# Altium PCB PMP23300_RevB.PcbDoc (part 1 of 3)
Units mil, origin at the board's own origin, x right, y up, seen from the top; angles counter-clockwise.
Board outline 3834 x 2383 mil, 4 copper layers (Top Layer 1, Signal Layer 2, Signal Layer 3, Bottom Layer 1), stack 70.112 mil thick; 203 components, 126 nets, 635 pads, 226 vias.
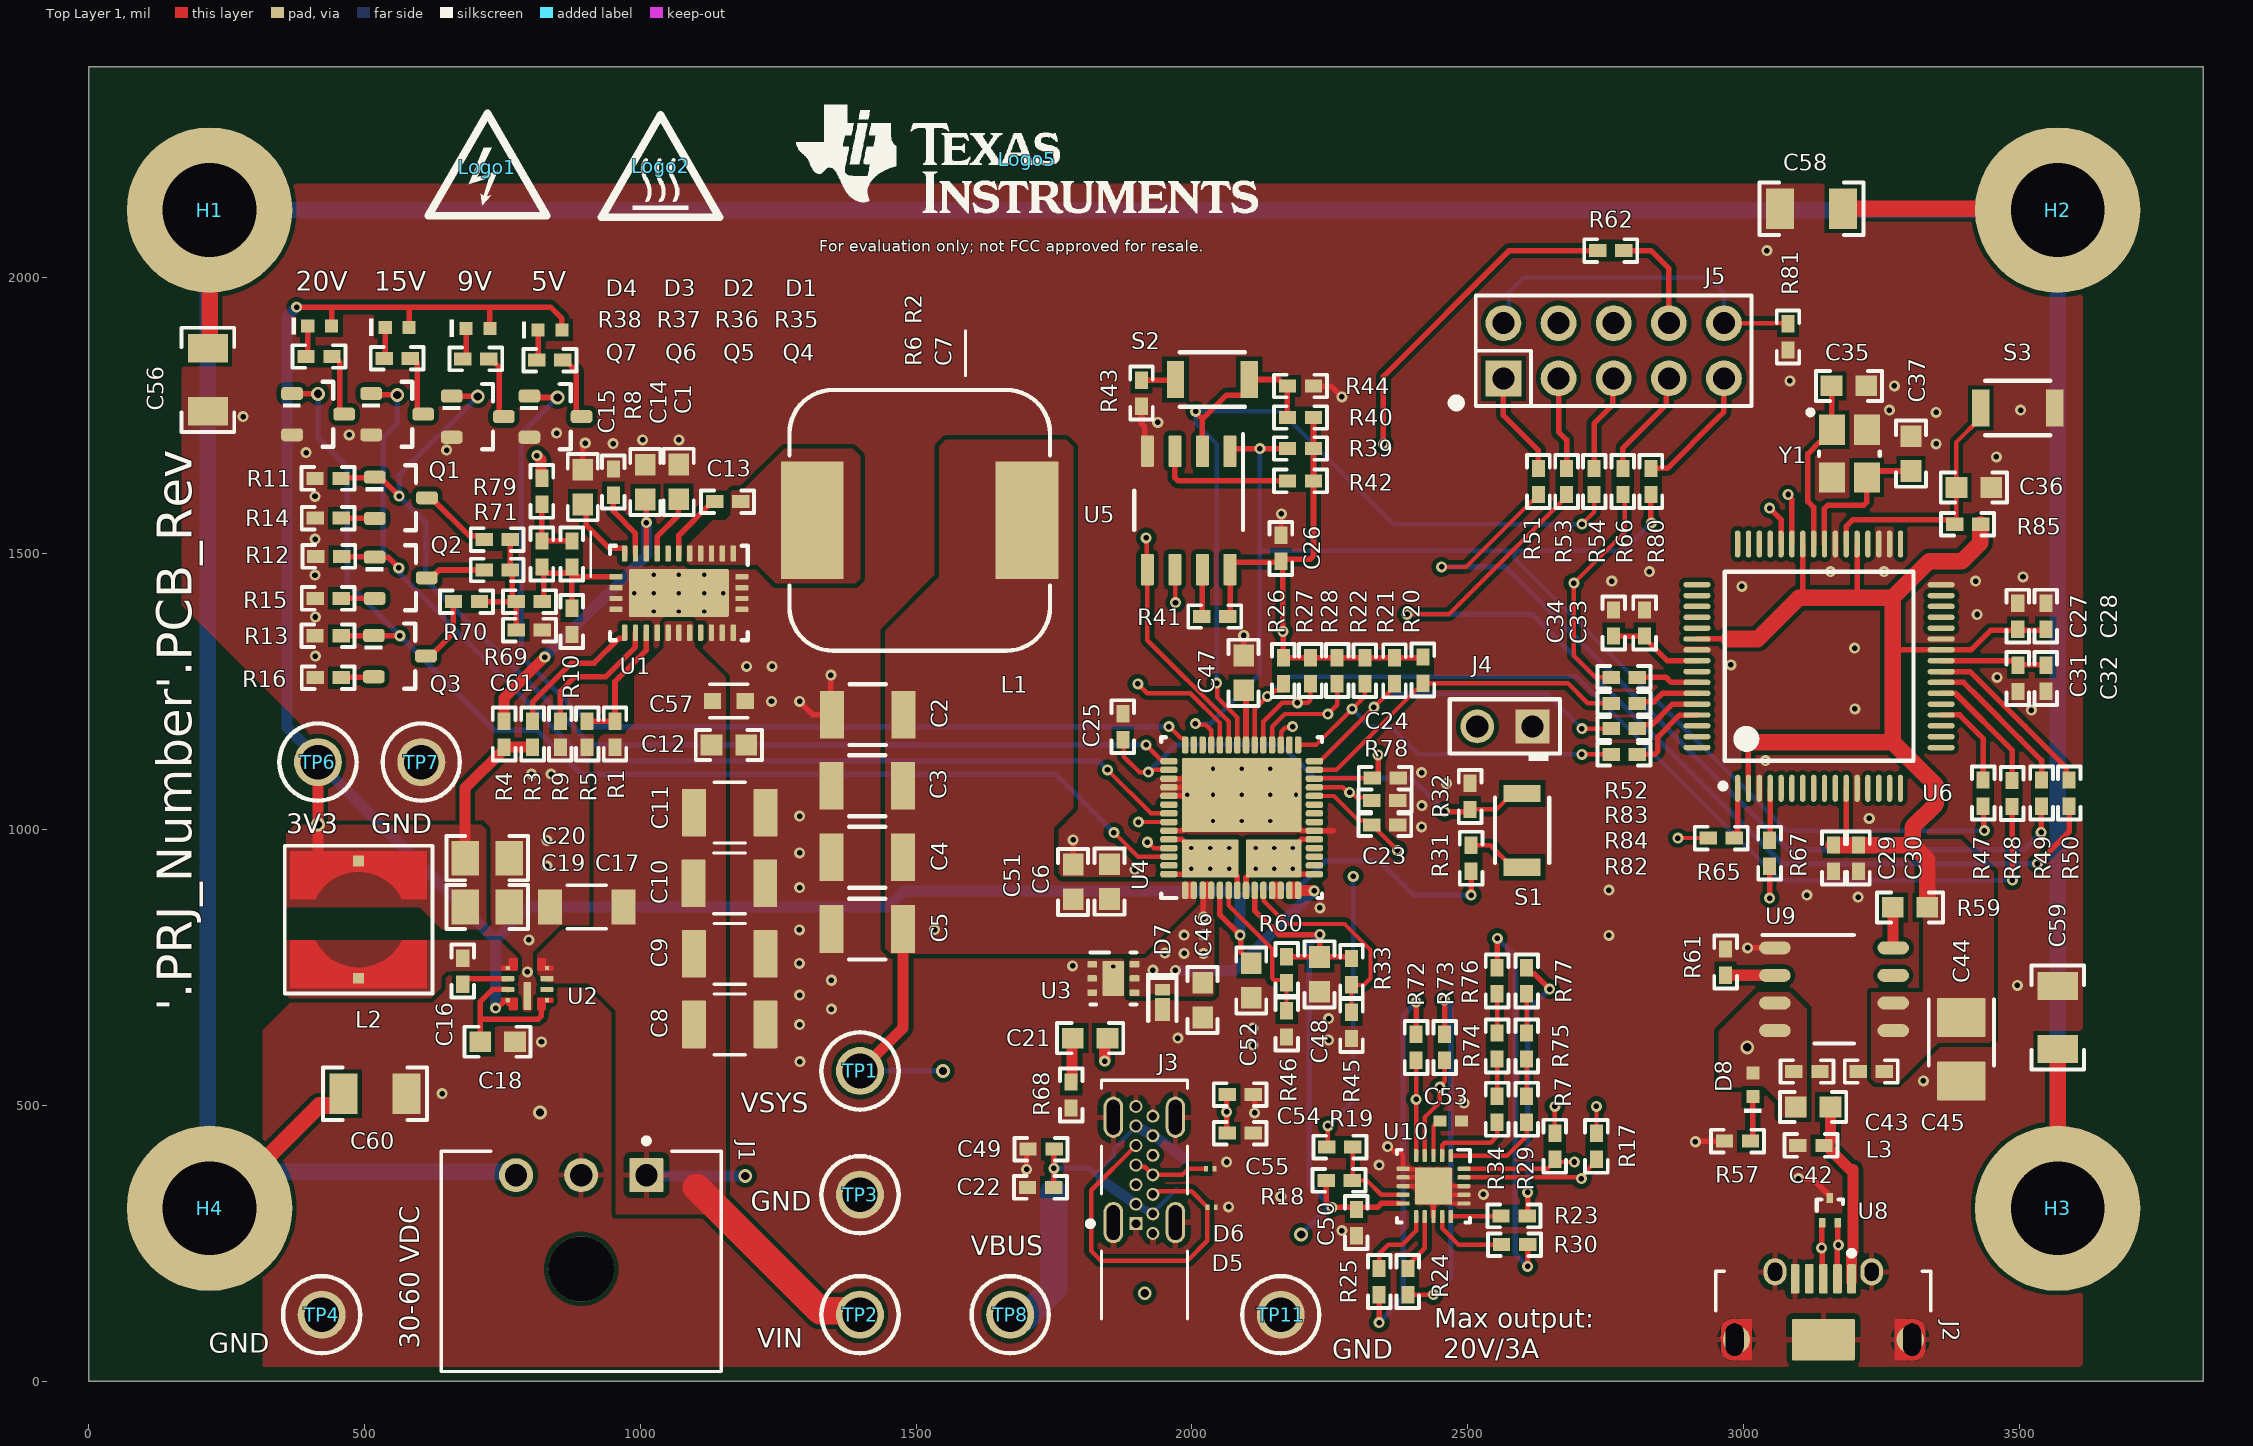
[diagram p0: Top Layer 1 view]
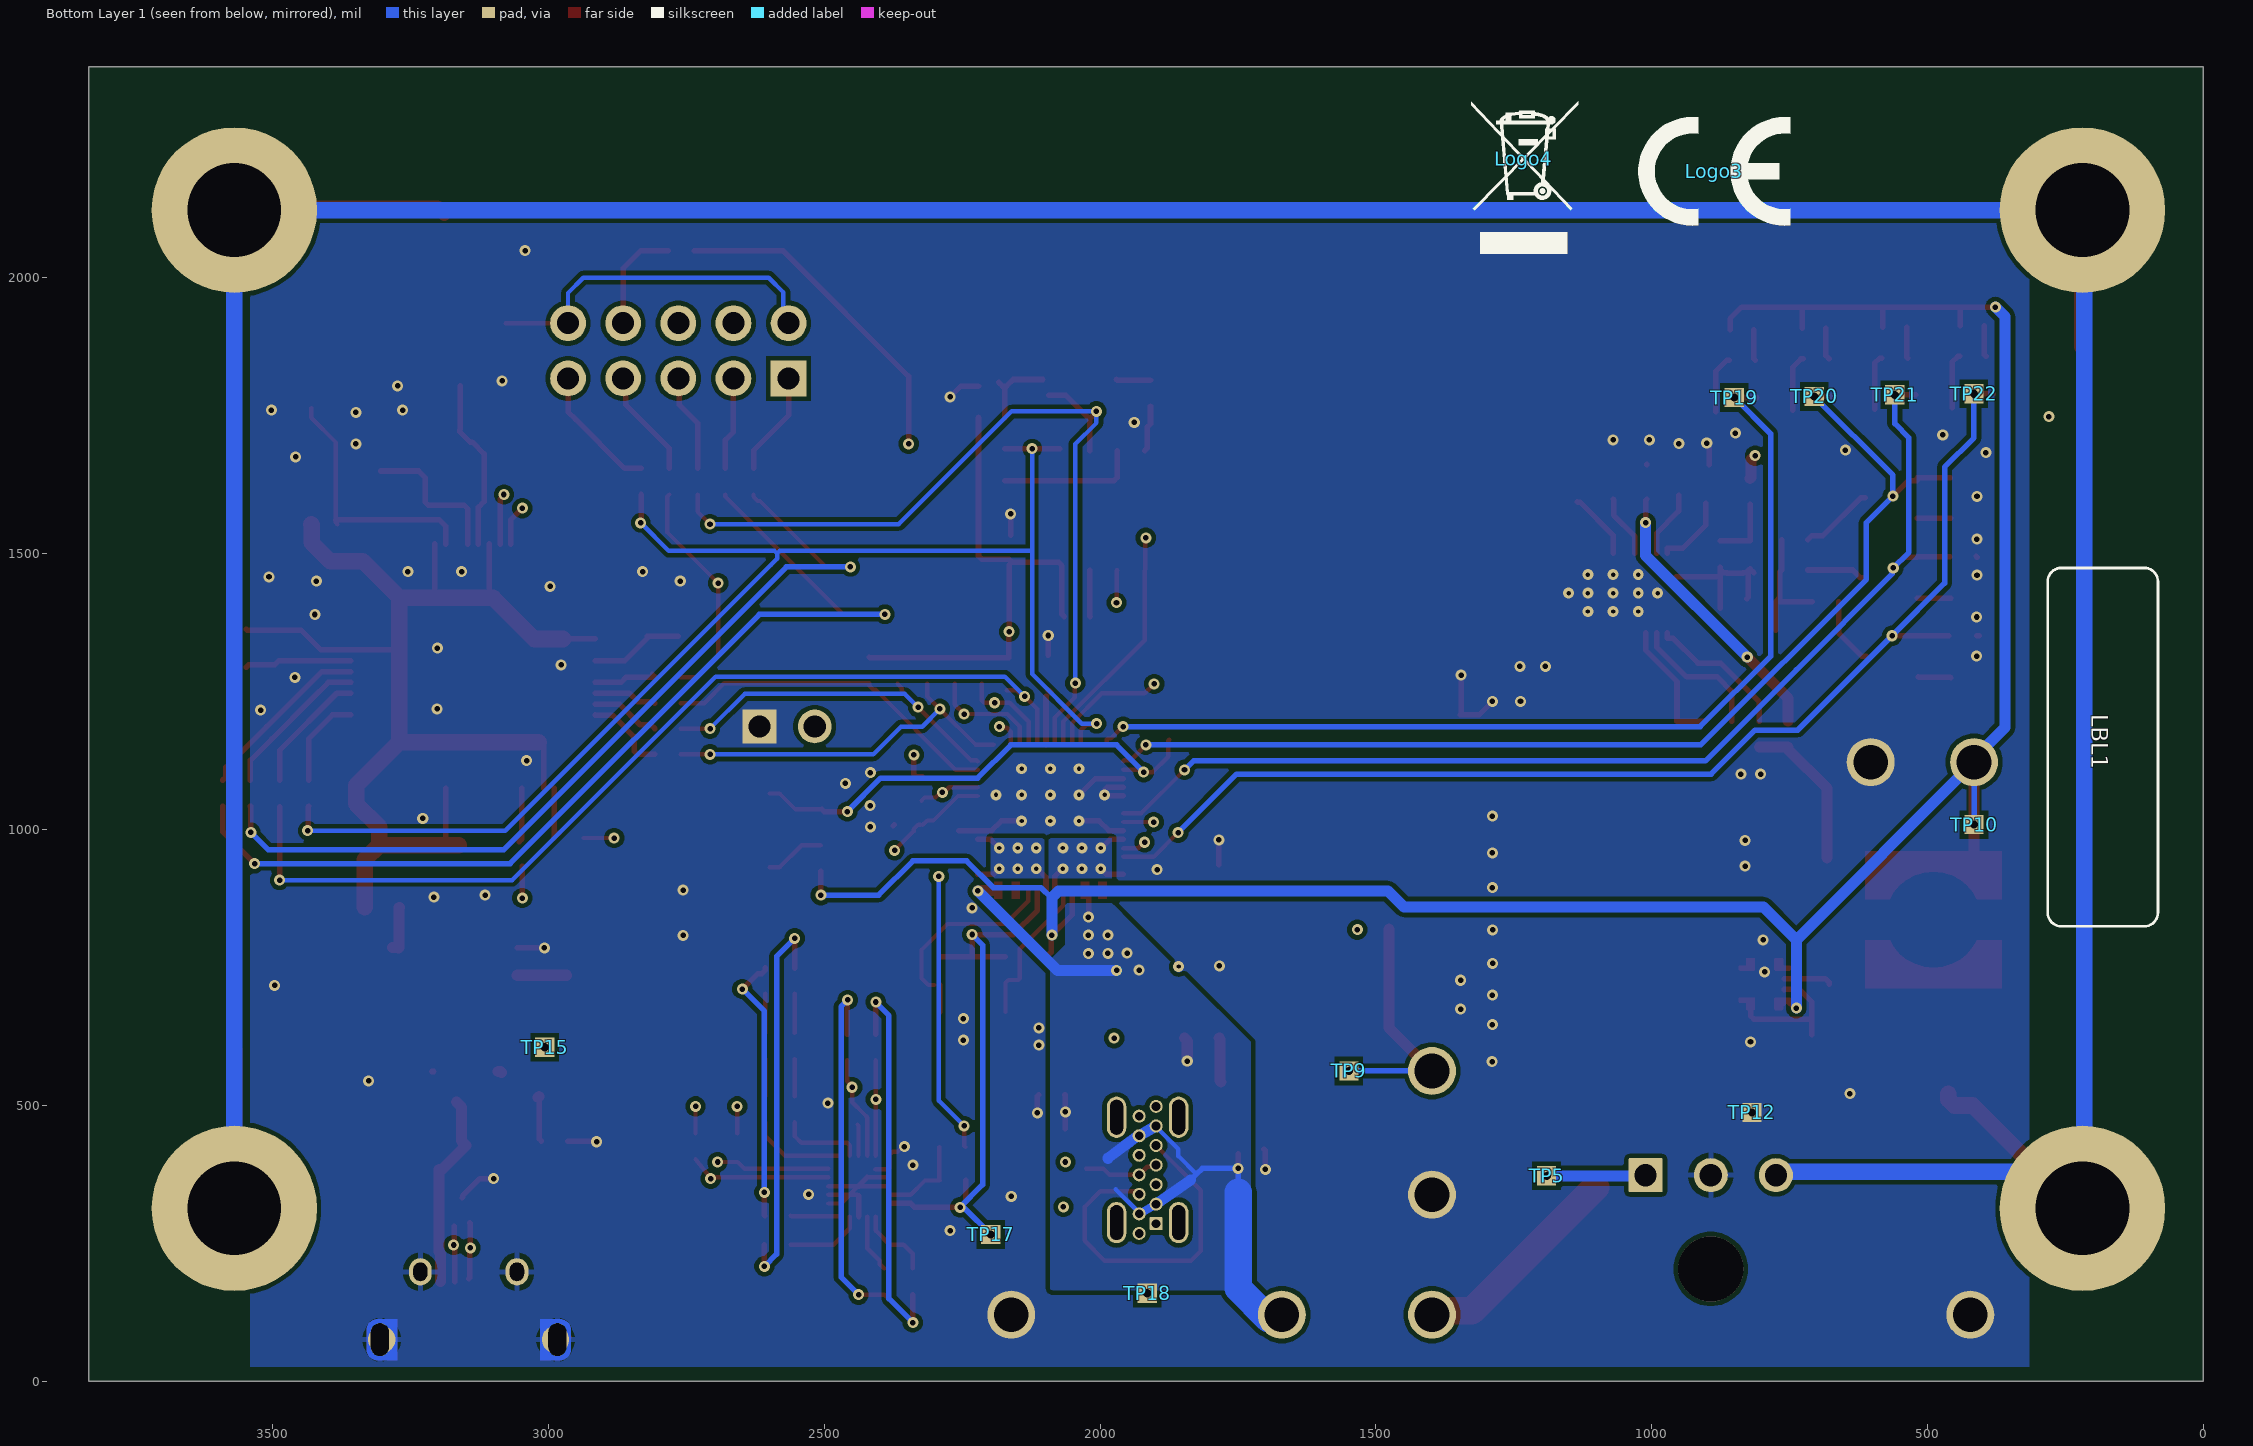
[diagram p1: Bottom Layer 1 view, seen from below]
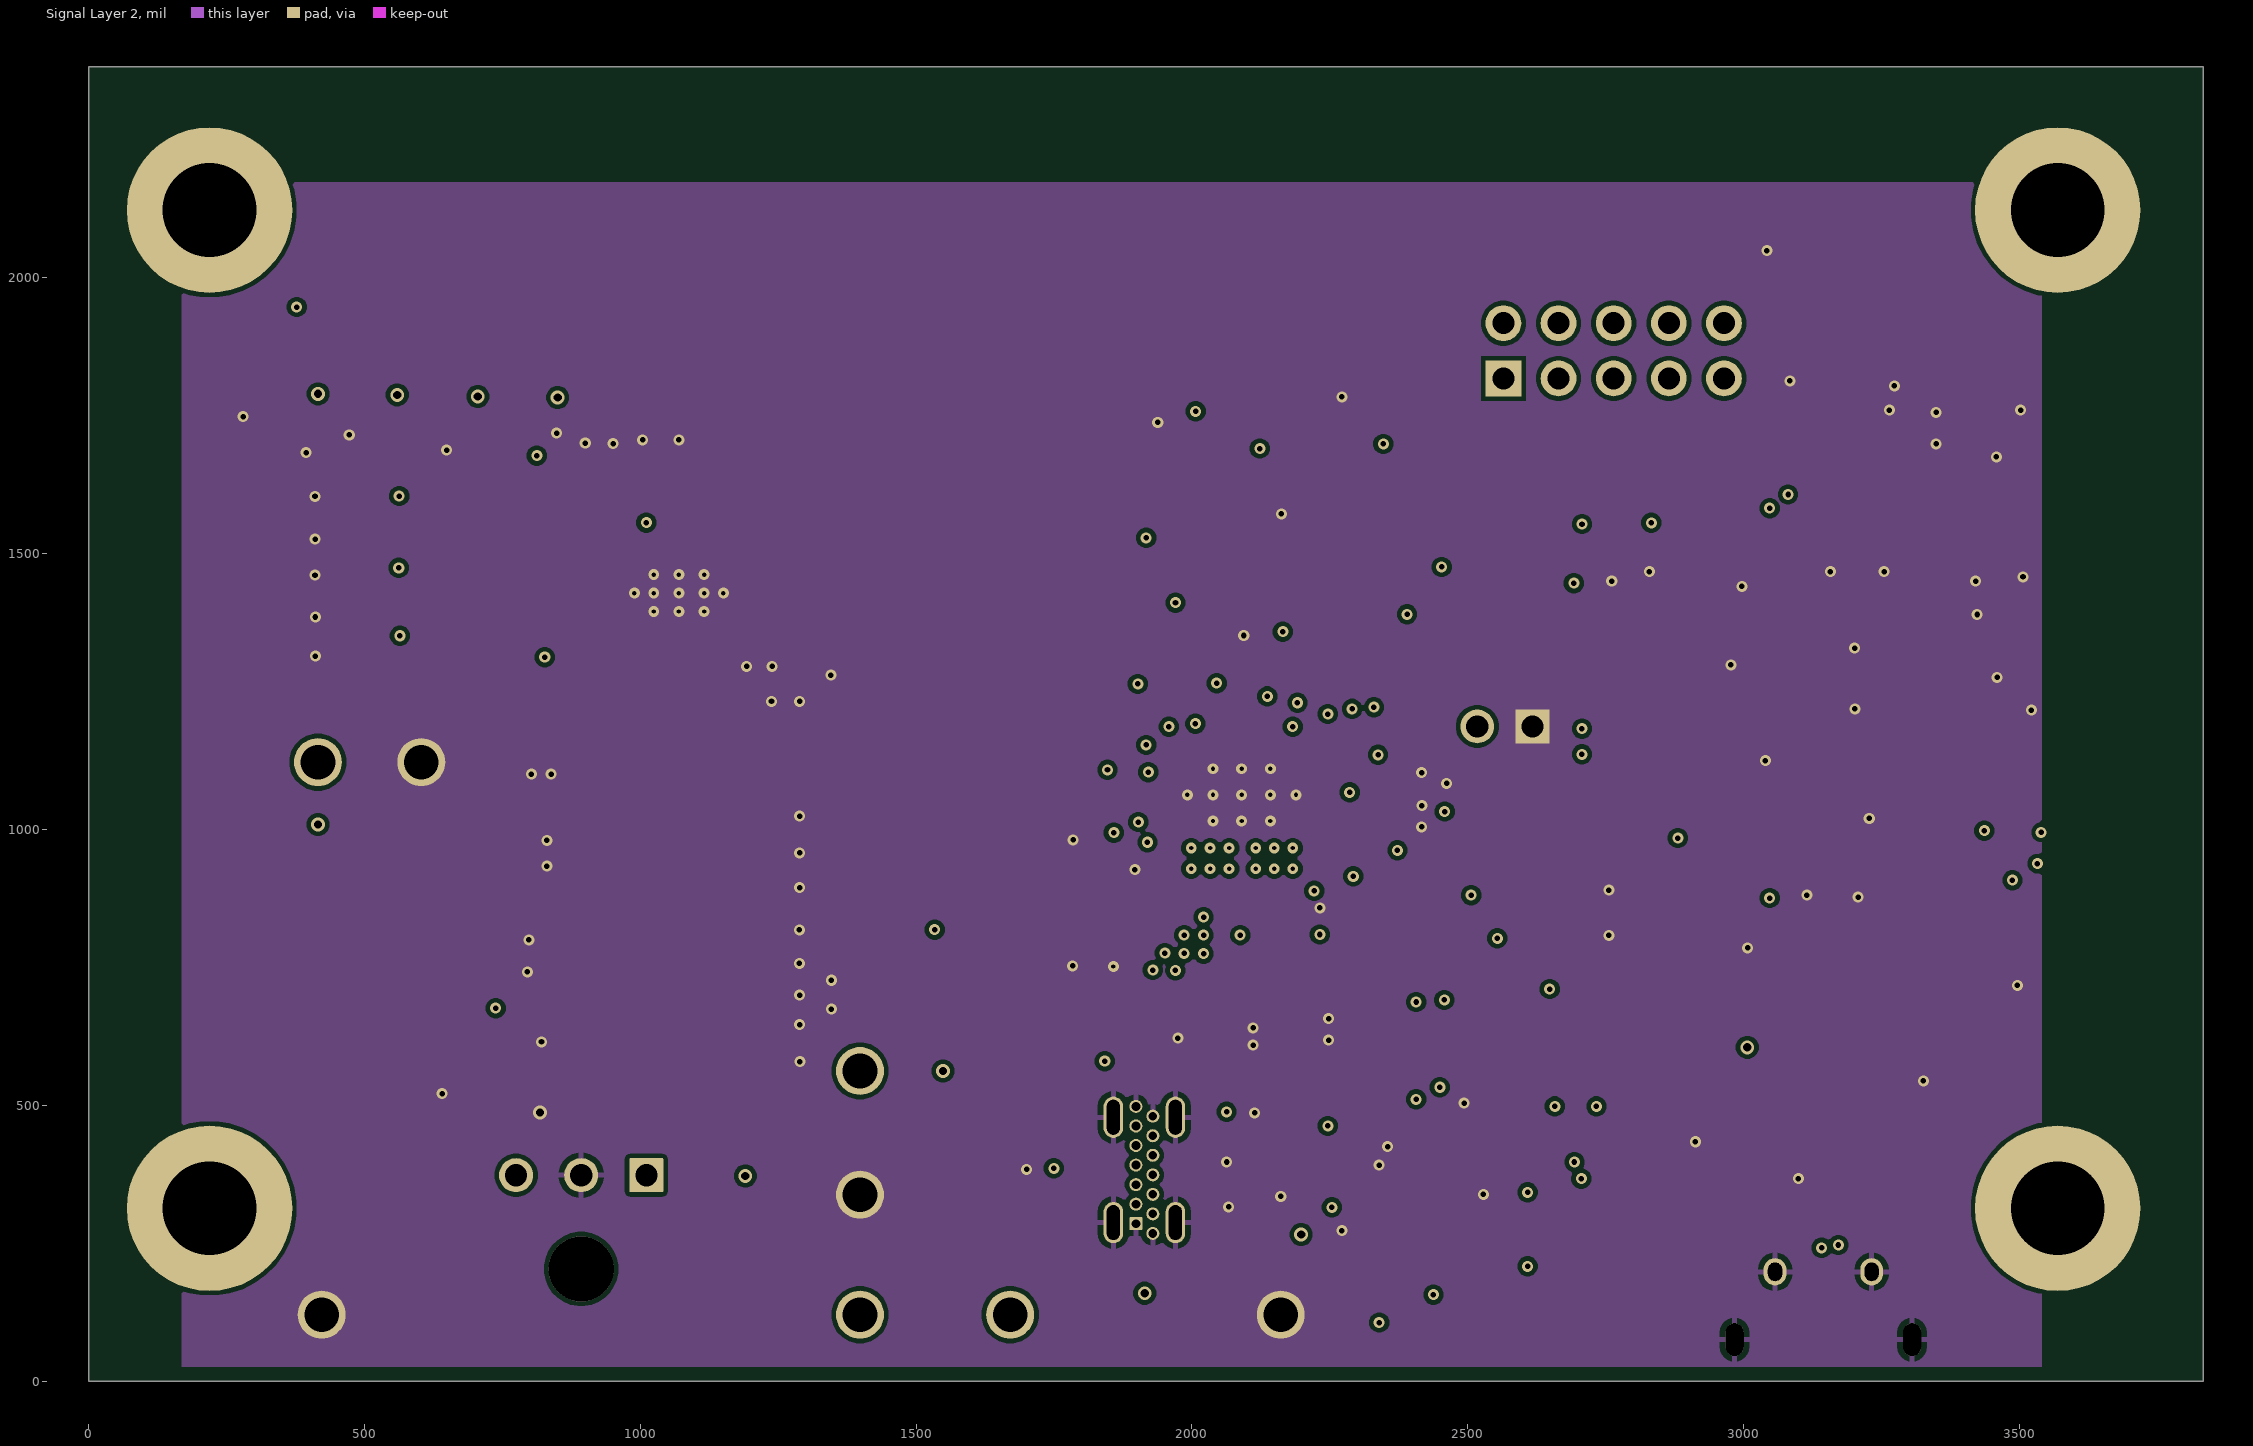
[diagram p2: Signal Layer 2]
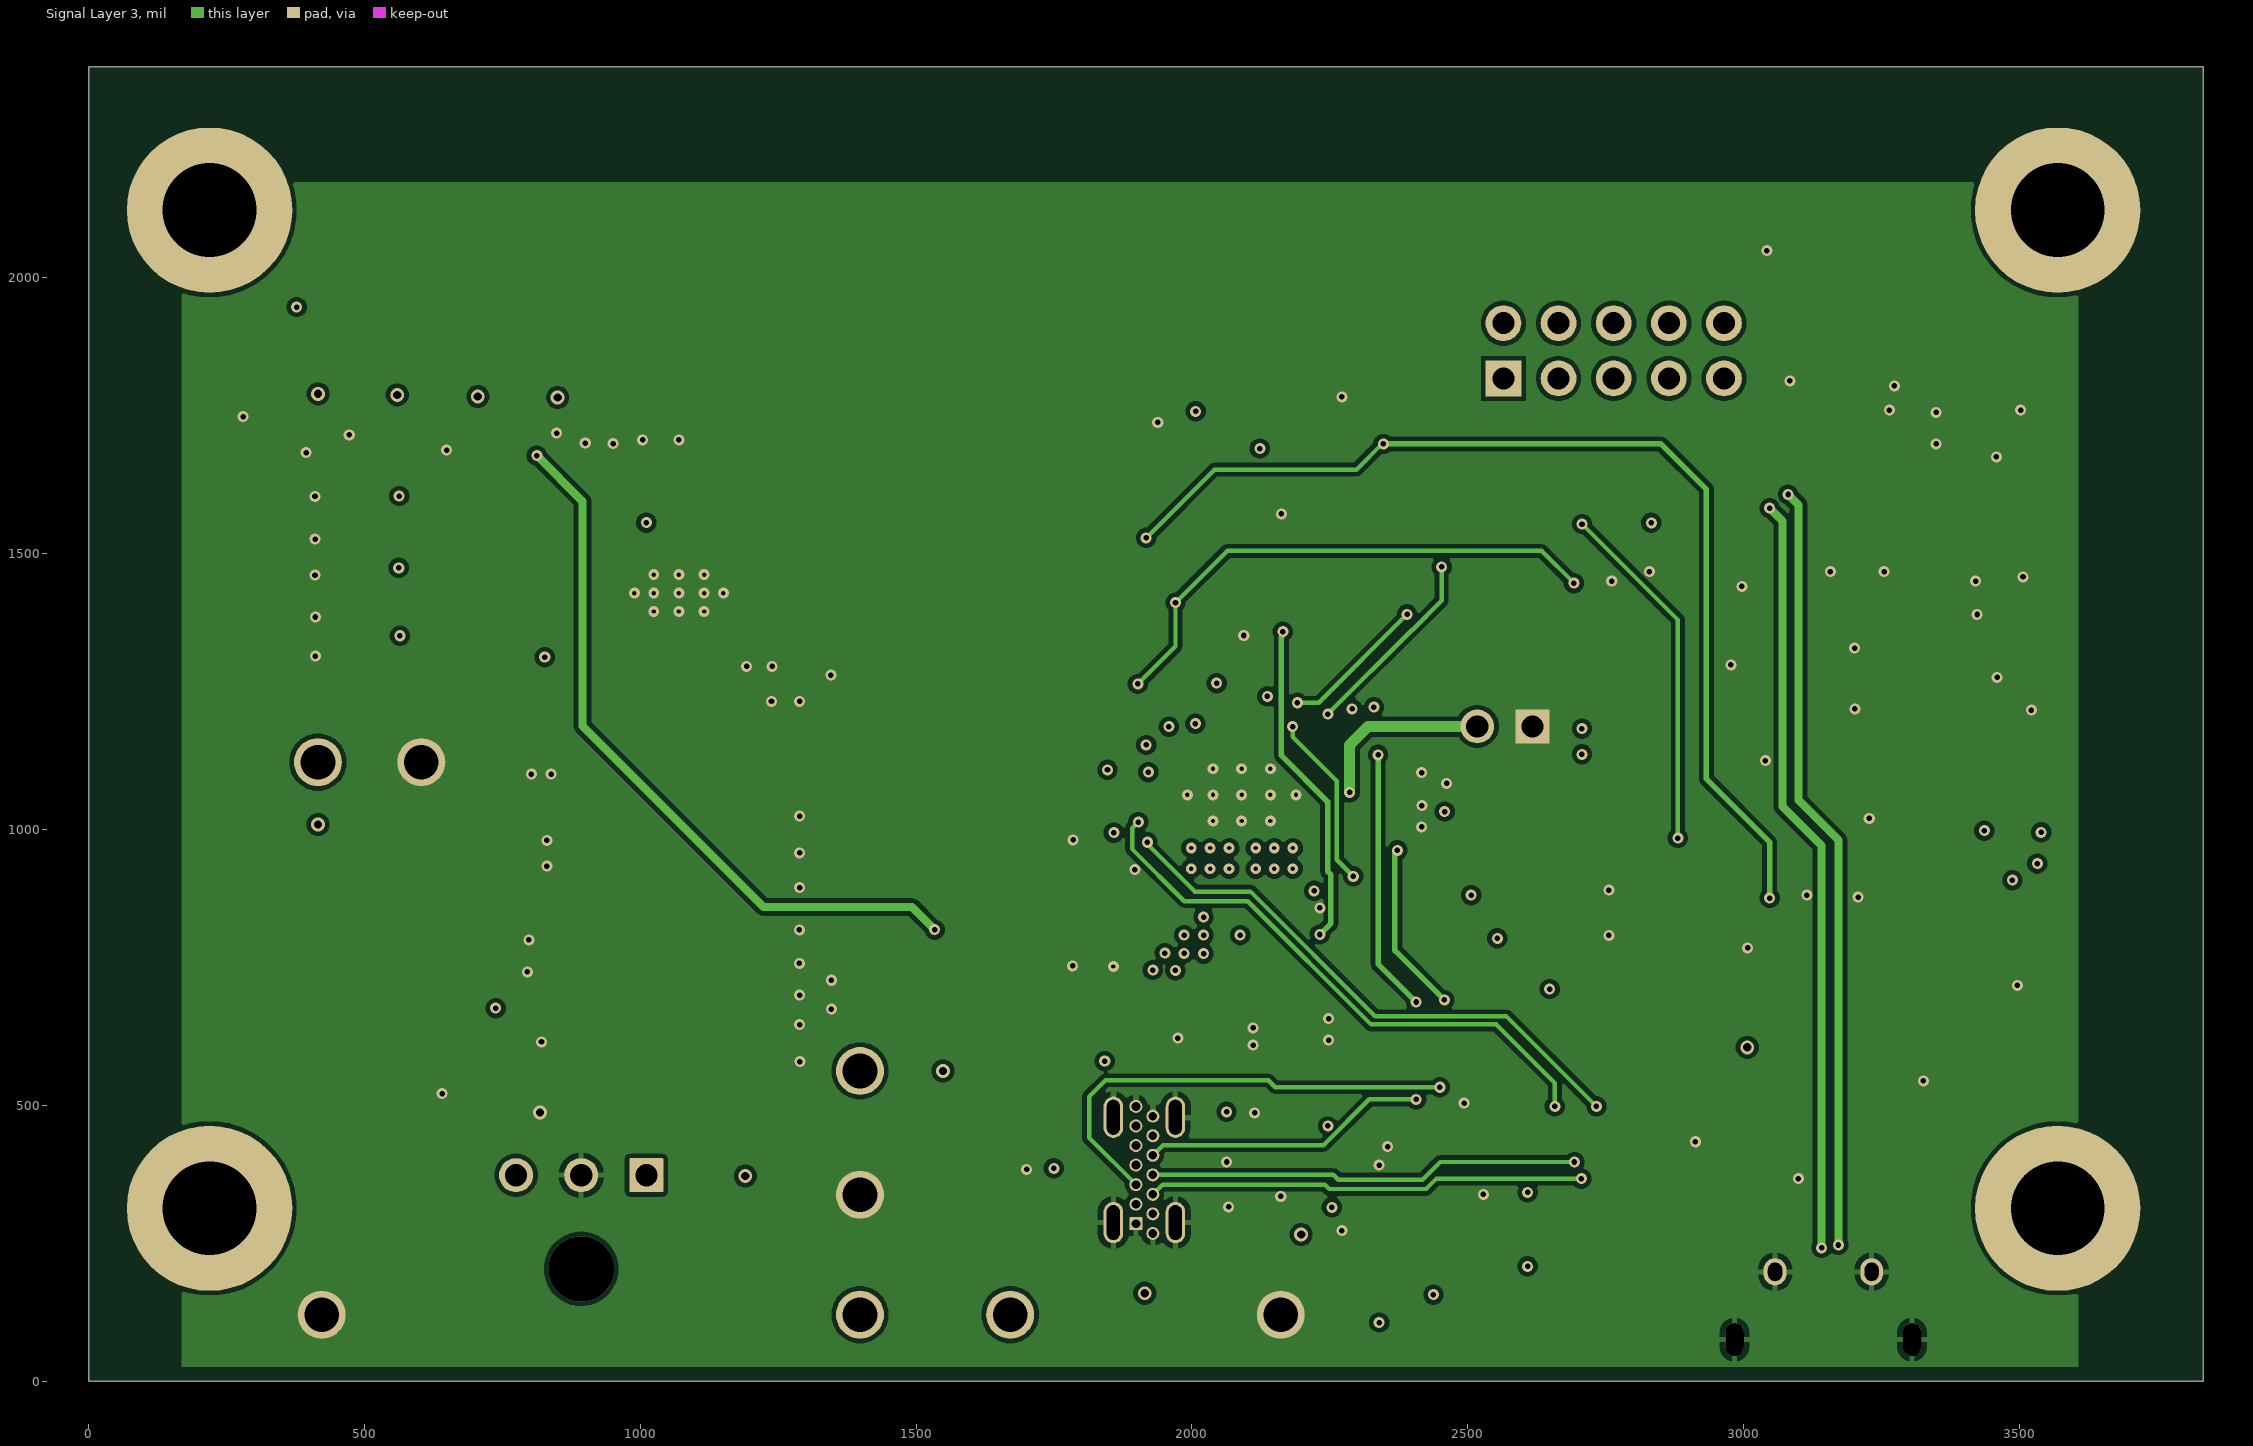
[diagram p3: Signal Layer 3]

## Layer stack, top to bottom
Top Solder: solder mask 1, SM-001, Dk 4
Top Layer 1: signal copper 1.378
Dielectric 2: prepreg 2.8, PP-006, Dk 4.1
Signal Layer 2: signal copper 1.378
Dielectric 1: core 59, Core-043, Dk 4.3
Signal Layer 3: signal copper 1.378
Dielectric 3: prepreg 2.8, PP-006, Dk 4.1
Bottom Layer 1: signal copper 1.378
Bottom Solder: solder mask 1, SM-001, Dk 4

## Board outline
0,0 3834,0 3834,2383 0,2383

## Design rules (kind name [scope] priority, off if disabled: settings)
AcuteAngle [All] p1: minimum=4.50000000000000E+0001 checktracksonly=FALSE
AssemblyTestPointUsage [All] p1: valid=2
BoardOutlineClearance BoardOutlineClearance_MountingHoles [OnCopper and InComponentClass('Mounting Holes')] p1: gap=25 ignorepadtopadclearanceinfootprint=FALSE
BoardOutlineClearance BoardOutlineClearance_Poly [OnCopper and InPoly] p2: gap=25 ignorepadtopadclearanceinfootprint=FALSE
BoardOutlineClearance [OnCopper and Not InComponentClass('Logo') and not InComponentClass('FiducialMark') and not InRegion(1000,500,4000,800)] p3: gap=25 ignorepadtopadclearanceinfootprint=FALSE
Clearance Clearance_Keepouts [((IsTrack Or IsArc) And Not InPoly) And IsFree and IsKeepOut vs ((IsTrack Or IsArc) And Not InPoly) And IsFree and IsKeepOut] p1: gap=0 ignorepadtopadclearanceinfootprint=FALSE
Clearance Clearance_Poly [InPolygon] p2: gap=8 ignorepadtopadclearanceinfootprint=FALSE except(0: Arc-Hole Track-Hole SMDPad-Hole THPad-Hole Via-Hole Fill-Hole Poly-Hole Region-Hole Text-Hole)
Clearance Clearance_FiducialMark [IsKeepOut and InComponentClass('FiducialMark') vs IsPad and InComponentClass('FiducialMark')] p3: gap=0 ignorepadtopadclearanceinfootprint=FALSE
Clearance [All] p4: gap=5 ignorepadtopadclearanceinfootprint=TRUE except(0: Arc-Hole Track-Hole SMDPad-Hole THPad-Hole Via-Hole Fill-Hole Poly-Hole Region-Hole Text-Hole)
ComponentClearance ComponentClearance_MountingHoles_FiducialMarks [InComponentClass('Mounting Holes') vs InComponentClass('FiducialMark')] p1: gap=50 collisioncheckmode=3 verticalgap=10 showdistances=FALSE
ComponentClearance ComponentClearance_Shunt [InComponentClass('Header') vs InComponentClass('Shunt')] p2: gap=0 collisioncheckmode=3 verticalgap=0 showdistances=FALSE
ComponentClearance ComponentClearance_Logo [InComponentClass('Logo')] p3: gap=50 collisioncheckmode=3 verticalgap=10 showdistances=FALSE
ComponentClearance ComponentClearance_ScrewToNut [(HasFootprint('NY PMS 440 0025 PH')) vs (HasFootprint('Keystone_1902C'))] p4: gap=5 collisioncheckmode=3 verticalgap=10 showdistances=FALSE
ComponentClearance ComponentClearance_MountingHoles [InComponentClass('Mounting Holes')] p5: gap=50 collisioncheckmode=3 verticalgap=100000 showdistances=FALSE
ComponentClearance ComponentClearance_SmallPassives [HasFootprint('0201*') or HasFootprint('0402*') or HasFootprint('0508') or HasFootprint('0603*') or HasFootprint('0612') or HasFootprint('0805*') or HasFootprint('0815*') or HasFootprint('0830*') or HasFootprint('1206*') or HasFootprint('1210*') or HasFootprint('1808*') or HasFootprint('1812*') or HasFootprint('1825*') or HasFootprint('2010*') or HasFootprint('2220*') or HasFootprint('2225*') or HasFootprint('2512*') or HasFootprint('2728*') or HasFootprint('3518*') vs HasFootprint('0201*') or HasFootprint('0402*') or HasFootprint('0508') or HasFootprint('0603*') or HasFootprint('0612') or HasFootprint('0805*') or HasFootprint('0815*') or HasFootprint('0830*') or HasFootprint('1206*') or HasFootprint('1210*') or HasFootprint('1808*') or HasFootprint('1812*') or HasFootprint('1825*') or HasFootprint('2010*') or HasFootprint('2220*') or HasFootprint('2225*') or HasFootprint('2512*') or HasFootprint('2728*') or HasFootprint('3518*')] p6: gap=14.96 collisioncheckmode=3 verticalgap=10 showdistances=FALSE
ComponentClearance ComponentClearance_THtoSMT [IsThruComponent vs IsSMTComponent] p7: gap=15 collisioncheckmode=3 verticalgap=30 showdistances=FALSE
ComponentClearance ComponentClearance_THtoTH [IsThruComponent vs IsThruComponent] p8: gap=15 collisioncheckmode=3 verticalgap=30 showdistances=FALSE
ComponentClearance [All] p9: gap=15 collisioncheckmode=3 verticalgap=10 showdistances=FALSE
DiffPairsRouting [All] p1: maxlimit=100 minlimit=10 mostfreqgap=10 toplayer_minwidth=15 toplayer_maxwidth=15 toplayer_prefwidth=15 midlayer1_minwidth=15 midlayer1_maxwidth=15 midlayer1_prefwidth=15 midlayer2_minwidth=15 midlayer2_maxwidth=15 midlayer2_prefwidth=15 bottomlayer_minwidth=15 bottomlayer_maxwidth=15 bottomlayer_prefwidth=15 maxuncoupledlength=1000
FabricationTestPointUsage TestPointUsage [All] p1: valid=2 allowmultiple=FALSE
FabricationTestpoint Testpoint [All] p1: side=3 testpointundercomponent=TRUE minsize=40 maxsize=100 preferedsize=60 minholesize=0 maxholesize=40 preferedholesize=32 testpointgrid=1 allowsidetop=TRUE allowsidebottom=TRUE usegrid=TRUE gridtolerance=0.01
FanoutControl Fanout_LCC [IsLCC] p1: bgadir=Out bgaviamode=Centered fanoutstyle=Auto fanoutdirection=Alternating viagrid=1 // Fanout_LCC (Default Rule)
FanoutControl Fanout_BGA [IsBGA] p2: bgadir=Out bgaviamode=Centered fanoutstyle=Auto fanoutdirection=Alternating viagrid=1 // Fanout_BGA (Default Rule)
FanoutControl Fanout_Default [All] p4: bgadir=Out bgaviamode=Centered fanoutstyle=Auto fanoutdirection=Alternating viagrid=1 // Fanout_Default (Default Rule)
FanoutControl Fanout_Small [(CompPinCount < 5)] p5: bgadir=Out bgaviamode=Centered fanoutstyle=Auto fanoutdirection=OutThenIn viagrid=1 // Fanout_Small (Default Rule)
HoleSize [All] p1: absolutevalues=TRUE maxlimit=251 minlimit=7.87 maxpercent=80.000 minpercent=20.000
MinimumAnnularRing MinimumAnnularRing_ThermalPadVias [IsVia and InAnyComponent] p1: minimumring=5.91
MinimumAnnularRing [All] p2: minimumring=5
MinimumSolderMaskSliver MinimumSolderMaskSliver_Logo [InComponentClass('Logo') vs InComponentClass('Logo')] p1: minsoldermaskwidth=0.7
MinimumSolderMaskSliver [All] p2: minsoldermaskwidth=3.94
PlaneConnect [All] p1: planeconnectstyle=Direct reliefexpansion=10 reliefentries=4 reliefconductorwidth=10 reliefairgap=10
PolygonConnect PolygonConnect_3 [HasFootprint('FP-ZX62RD-AB-5P8(30)_CONN_USB-MFG')] p1: connectstyle=Relief reliefconductorwidth=10 reliefentries=4 polygonreliefangle="90 Angle" airgapwidth=10
PolygonConnect PolygonConnect_2 [HasFootprint('FP-12402054M611A_CONN_USB-MFG')] p2: connectstyle=Relief reliefconductorwidth=10 reliefentries=4 polygonreliefangle="90 Angle" airgapwidth=10
PolygonConnect PolygonConnect_1 [HasFootprint('FP-0436500301_CONN_HDR3-MFG')] p3: connectstyle=Relief reliefconductorwidth=10 reliefentries=4 polygonreliefangle="90 Angle" airgapwidth=10
PolygonConnect [All] p4: connectstyle=Direct reliefconductorwidth=10 reliefentries=4 polygonreliefangle="90 Angle" airgapwidth=10
RoutingVias ThermalPadVias [IsVia and InAnyComponent] p1: holewidth=7.87 width=19.68 viastyle="Through Hole" minholewidth=7.87 minwidth=19.68 maxholewidth=12.99 maxwidth=23.62
RoutingVias [All] p2: holewidth=16 width=34 viastyle="Through Hole" minholewidth=5 minwidth=10 maxholewidth=40 maxwidth=65
SilkToBoardRegionClearance [Not ((IsComment or IsDesignator) And (Hide <> 'False')) and not InRegion(1000,500,4000,800)] p1:
SilkToSilkClearance SilkToSilkClearance_Pb-FreeLogo [(HasFootprint('Pb-Free_Overlay_Medium') OR HasFootprint('Pb-Free_Overlay_Small')) vs (HasFootprint('Pb-Free_Overlay_Medium') OR HasFootprint('Pb-Free_Overlay_Small'))] p1: silktosilkclearance=0
SilkToSilkClearance [All] p2: silktosilkclearance=4
SilkToSolderMaskClearance SilkToComponentPadClearance [IsPad and InAnycomponent] p1: minsilkscreentomaskgap=5 clearancetoexposedcopper=TRUE
SilkToSolderMaskClearance "Silk to Solder Mask Opening" [All] p2: minsilkscreentomaskgap=4 clearancetoexposedcopper=FALSE
SolderMaskExpansion [All] p1: expansion=1.97 istentingtop=FALSE
Width [All] p1: maxlimit=100 minlimit=6 preferedwidth=10 checkconnectedcopper=TRUE
15 further rules are at their usual default settings.

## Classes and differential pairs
component class Header: J5
component class "Mounting Holes": H1 H2 H3 H4
component class PMP23300_PD_Power_RevB: C21 C22 C46 C47 C48 C49 C50 C51 C52 C53 C54 C55 D5 D6 D7 J3 J4 R18 R19 R23 R24 R25 R29 R30 R34 R68 R72 R73 R74 R75 R76 R77 R78 TP8 TP11 TP17 TP18 U3 U10
component class PMP23300_PD_Control_RevB: C23 C24 C25 C26 R7 R17 R20 R21 R22 R26 R27 R28 R31 R32 R33 R39 R40 R41 R42 R43 R44 R45 R46 R60 S1 S2 U4 U5
component class PMP23300_TIVA_RevB: C27 C28 C29 C30 C31 C32 C33 C34 C35 C36 C37 C42 C43 C44 C45 D8 J2 J5 L3 R47 R48 R49 R50 R51 R52 R53 R54 R57 R59 R61 R62 R65 R66 R67 R80 R81 R82 R83 R84 R85 S3 TP15 U6 U8 U9 Y1
component class Logo: Logo5
component class Label: LBL1
differential pair F_USB_D: +F_USB_D_P -F_USB_D_N

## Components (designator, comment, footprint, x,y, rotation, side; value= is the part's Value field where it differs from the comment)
C1 "GRM188R71A225KE15D" 0603 1069.71,1630.34 r90 top value=2.2uF
C2 "C1210C226K3RAC7800" 1210_280 1412.39,1208.23 r180 top value=22uF
C3 "C1210C226K3RAC7800" 1210_280 1411.37,1079.41 r180 top value=22uF
C4 "C1210C226K3RAC7800" 1210_280 1411.37,949.72 r180 top value=22uF
C5 "C1210C226K3RAC7800" 1210_280 1411.37,819.51 r180 top value=22uF
C6 "C1608X5R1H105K080AB" 0603 1850.73,905.29 r90 top value=1uF
C7 "04025A101FAT2A" 0402 875.82,1499.52 r270 top value=100pF
C8 "CNC6P1X7R2A475K250AE" FP-CNC6P1X7R2A475K250AE_1210-MFG 1162.21,646.56 r180 top value=4.7µF
C9 "CNC6P1X7R2A475K250AE" FP-CNC6P1X7R2A475K250AE_1210-MFG 1162.21,774.51 r180 top value=4.7µF
C10 "CNC6P1X7R2A475K250AE" FP-CNC6P1X7R2A475K250AE_1210-MFG 1161.63,902.46 r180 top value=4.7µF
C11 "CNC6P1X7R2A475K250AE" FP-CNC6P1X7R2A475K250AE_1210-MFG 1162.21,1030.41 r180 top value=4.7µF
C12 "C1608X7S2A473K080AB" 0603 1160.61,1153.11 r0 top value=0.047uF
C13 "GRM155R71E473KA88D" 0402 1158.44,1594.31 r180 top value=0.047uF
C14 "C1608X7R1V105K080AC" 0603 1009.12,1629.96 r90 top value=1uF
C15 "GRM188R71C103KA01D" 0603 895.72,1620.58 r90 top value=0.01uF
C16 "CC0402KRX7R8BB104" 0402 678.13,743.15 r270 top value=0.1uF
C17 "GRM31CR72A225KA73L" 1206_190 902.98,859.36 r180 top value=2.2uF
C18 "CL10B105KO8NFNC" 0603 741.25,615.08 r0 top value=1uF
C19 "GRM21BZ71A226ME15L" 0805_HV 722.61,859.36 r0 top value=22uF
C20 "GRM21BZ71A226ME15L" 0805_HV 722.61,947.94 r0 top value=22uF
C21 "GRM188R6YA475KE15D" 0603 1815.71,621.55 r0 top value=4.7uF
C22 "GCM155R71H103KA55D" 0402 1725.79,351.08 r180 top value=0.01uF
C23 "CC0402KRX7R9BB221" 0402 2349.99,1008.55 r0 top value=220pF
C24 "CC0402KRX7R9BB221" 0402 2350.83,1093.13 r0 top value=220pF
C25 "GCM155R71H103KA55D" 0402 1874.88,1186.41 r90 top value=0.01uF
C26 "885012205037" 0402 2161.66,1509.68 r90 top value=0.1uF
C27 "GCM155R71H104KE02D" 0402 3497.67,1386.73 r90 top value=0.1uF
C28 "GCM155R71H104KE02D" 0402 3548.57,1386.79 r90 top value=0.1uF
C29 "GCM155R71H104KE02D" 0402 3163.37,948.2 r270 top value=0.1uF
C30 "GCM155R71H104KE02D" 0402 3208.75,948.2 r270 top value=0.1uF
C31 "C1005X5R1A475M050BC" 0402 3497.71,1273.88 r270 top value=4.7uF
C32 "GCM155R71H104KE02D" 0402 3548.61,1274.01 r90 top value=0.1uF
C33 "C1005X5R1A475M050BC" 0402 2821.02,1374.41 r90 top value=4.7uF
C34 "GCM155R71H104KE02D" 0402 2765,1374.41 r270 top value=0.1uF
C35 "CGA3E2C0G1H100D080AA" 0603 3191.62,1804.29 r180 top value=10pF
C36 "06035A181JAT2A" 0603 3418,1620 r180 top value=180pF
C37 "CGA3E2C0G1H100D080AA" 0603 3304.2,1681.52 r270 top value=10pF
C42 "C0402C103J5RACTU" 0402 3122.67,427.06 r180 top value=0.01uF
C43 "GCM155R71H104KE02D" 0402 3115.45,561.2 r0 top value=0.1uF
C44 "293D106X9010B2TE3" 3528-21 3395.41,601.52 r270 top value=10uF
C45 "0402ZD106MAT2A" 0402_080 3232,561.2 r180 top value=10uF
C46 "UMK107AB7105KA-T" 0603 2019.59,690.72 r270 top value=1uF
C47 "JMK107BB7475MA-T" 0603 2093.91,1284.02 r90 top value=4.7uF
C48 "GRM188Z71A106MA73D" 0603 2231.67,737.44 r270 top value=10uF
C49 "GCM155R71H103KA55D" 0402 1726.76,420.43 r180 top value=0.01uF
C50 "EMK105BJ105KVHF" 0402 2298.4,287.23 r270 top value=1uF
C51 "GRM188R61E106MA73D" 0603 1784.93,904.92 r90 top value=10uF
C52 "GRM188Z71A106MA73D" 0603 2107.89,726.21 r270 top value=10uF
C53 "GCM155R71H104KE02D" 0402L 2469.72,471.52 r0 top value=0.1uF
C54 "GCM155R71H103KA55D" 0402 2087.75,519.34 r0 top value=0.01uF
C55 "GCM155R71H103KA55D" 0402 2087.75,449.27 r0 top value=0.01uF
C56 "" 1206 216.09,1815.38 r90 top value=0.047uF
C57 "06031C101JAT2A" FP-06031C101JAT2A_0603-MFG 1160.61,1232.95 r180 top value=100pF
C58 "" 1206 3123.69,2125.57 r0 top value=0.047uF
C59 "" 1206 3570.09,659 r270 top value=0.047uF
C60 "" 1206 519.06,520.97 r180 top value=0.047uF
C61 "JMK105B7474KVHF" 0402 798.98,1361.49 r0 top value=0.47uF
D1 "LW QH8G-Q2S2-3K5L-1" "LW QH8G_White" 836.38,1905.78 r180 top value=White
D2 "LW QH8G-Q2S2-3K5L-1" "LW QH8G_White" 705.73,1908.57 r180 top value=White
D3 "LW QH8G-Q2S2-3K5L-1" "LW QH8G_White" 559.29,1910.52 r180 top value=White
D4 "LW QH8G-Q2S2-3K5L-1" "LW QH8G_White" 418.76,1912.96 r180 top value=White
D5 "TPD1E01B04DPLR" DPL0002A 2035.82,315.02 r180 top
D6 "TPD1E01B04DPLR" DPL0002A 2033.41,384.9 r180 top
D7 "NSR20F30NXT5G" DSN2_0603 1946.77,684.22 r270 top value=30V
D8 "LW QH8G-Q2S2-3K5L-1" "LW QH8G_White" 3017.21,537.12 r270 top value=White
H1 "NY PMS 440 0025 PH" "NY PMS 440 0025 PH"#1 219.09,2123.1 r0 top
H2 "NY PMS 440 0025 PH" "NY PMS 440 0025 PH"#2 3556.42,2095.67 r180 top
H3 "NY PMS 440 0025 PH" "NY PMS 440 0025 PH"#1 3570.09,313.1 r0 top
H4 "NY PMS 440 0025 PH" "NY PMS 440 0025 PH"#3 213.09,385.45 r0 top
J1 "0436500301" FP-0436500301_CONN_HDR3-MFG 892.89,216.9 r0 top
J2 "ZX62RD-AB-5P8(30)" FP-ZX62RD-AB-5P8(30)_CONN_USB-MFG 3145.15,66.16 r0 top
J3 "12402054M611A" FP-12402054M611A_CONN_USB-MFG 1914.08,254.75 r0 top
J4 "HTSW-102-09-G-S" Samtec_HTSW-102-09-x-S 2567.67,1186.88 r180 top
J5 "PEC05DAAN" CONN_PEC05DAAN 2765,1868 r0 top
L1 "7447709330" WE-PD_1210 1506.73,1560.51 r0 top value=33uH
L2 "744053180" WE-TPC-LH 489.3,836.55 r90 top value=18uH
L3 "BLM18SG260TN1D" 0603 3126.6,496.86 r180 top value="26 ohm"
LBL1 "THT-14-423-10" Label_650x200 182.09,1149.34 r270 bottom
Logo1 "DANGER HIGH VOLTAGE" IEC_HighVoltage_Small 722.83,2201 r0 top (schematic designator LOGO1)
Logo2 "CAUTION HOT SURFACE" IEC_HotSurface_Small 1036.75,2203 r0 top
Logo3 "CE Mark" CE_Mark_5mm 886.58,2193.33 r180 bottom
Logo4 "WEEE logo" WEEE_Minimum 1232.2,2216 r180 bottom
Logo5 "Texas Instruments" TI_Stacked_Overlay_Small 1701.62,2215.5 r0 top
Logo6 "FCC disclaimer" FCC_disclaimer 6132.72,-1537.92 r90 top
Q1 "BSH105,215" SOT-23 565.94,1601.41 r0 top value=20V
Q2 "BSH105,215" SOT-23 565.69,1456.32 r0 top value=20V
Q3 "BSH105,215" SOT-23 564.21,1314.37 r0 top value=20V
Q4 "BSH105,215" SOT-23 846.23,1748.61 r0 top value=20V
Q5 "BSH105,215" SOT-23 705.45,1748.61 r0 top value=20V
Q6 "BSH105,215" SOT-23 559.29,1753.01 r0 top value=20V
Q7 "BSH105,215" SOT-23 415.85,1753.01 r0 top value=20V
R1 "CRCW0402300KFKED" 0402 954.2,1172.96 r270 top value=300k
R2 "CRCW04020000Z0EDHP" 0402 821.8,1613.21 r270 top value=0
R3 "RC1005F104CS" 0402 804.71,1172.96 r90 top value=100k
R4 "CRCW04020000Z0EDHP" 0402 753.06,1172.96 r90 top value=0
R5 "CRCW040212K7FKED" 0402 903.78,1172.96 r90 top value=12.7k
R6 "RC1005F104CS" 0402 821.8,1499.52 r90 top value=100k
R7 "RC0402JR-070RL" 0402 2658.25,425.65 r270 top value=0
R8 "RC1005F104CS" 0402 951.19,1629.96 r270 top value=100k
R9 "CRCW04020000Z0EDHP" 0402 855.02,1172.96 r270 top value=0
R10 "CRCW040224K9FKED" 0402 875.82,1377.21 r90 top value=24.9k
R11 "RC1005F104CS" 0402 433.85,1636.55 r0 top value=100k
R12 "RC1005F104CS" 0402 435.34,1495.1 r0 top value=100k
R13 "RC1005F104CS" 0402 433.97,1351.29 r0 top value=100k
R14 "CRCW04020000Z0EDHP" 0402 434.1,1564.42 r180 top value=0
R15 "CRCW04020000Z0EDHP" 0402 434.1,1419.02 r180 top value=0
R16 "CRCW04020000Z0EDHP" 0402 434.1,1275.25 r180 top value=0
R17 "RC0402JR-070RL" 0402 2733.79,425.55 r270 top value=0
R18 "CRCW0402100KFKED" 0402 2267.11,363.62 r180 top value=100k
R19 "RC0402JR-070RL" 0402 2268.49,424.22 r180 top value=0
R20 "CRCW04023K83FKED" 0402 2419.15,1289.03 r270 top value=3.83k
R21 "CRCW04023K83FKED" 0402 2367.59,1287.85 r270 top value=3.83k
R22 "ERJ-2RKF1002X" 0402 2313.75,1287.97 r270 top value=10.0k
R23 "RC0402JR-070RL" 0402 2584.4,299.41 r180 top value=0
R24 "RC0402JR-070RL" 0402 2391.79,180.32 r90 top value=0
R25 "RC0402JR-070RL" 0402 2339.79,180.32 r90 top value=0
R26 "ERJ-2RKF1002X" 0402 2165.9,1288.1 r270 top value=10.0k
R27 "CRCW04023K83FKED" 0402 2215.12,1288.1 r270 top value=3.83k
R28 "CRCW04023K83FKED" 0402 2263.57,1288.1 r270 top value=3.83k
R29 "RC0402JR-070RL" 0402 2607.18,492.75 r90 top value=0
R30 "RC0402JR-070RL" 0402 2585.26,247.25 r180 top value=0
R31 "RC0402JR-070RL" 0402 2506.48,947.78 r270 top value=0
R32 "CRCW0402100KFKED" 0402 2504.51,1059.99 r270 top value=100k
R33 "CRCW0402191KFKED" 0402 2289.62,742.37 r90 top value=191k
R34 "RC0402JR-070RL" 0402 2553.51,492.75 r90 top value=0
R35 "ERJ-2RKF1002X" 0402 836.09,1850.99 r180 top value=10.0k
R36 "ERJ-2RKF1002X" 0402 701.79,1853.25 r180 top value=10.0k
R37 "ERJ-2RKF1002X" 0402 559.29,1854.35 r180 top value=10.0k
R38 "ERJ-2RKF1002X" 0402 417.5,1857.65 r180 top value=10.0k
R39 "CRCW04023K30JNED" 0402 2197.09,1690.79 r180 top value=3.3k
R40 "CRCW04023K30JNED" 0402 2197.09,1747.03 r180 top value=3.3k
R41 "CRCW04023K30JNED" 0402 2041.61,1386.19 r0 top value=3.3k
R42 "CRCW04023K30JNED" 0402 2197.09,1631.99 r180 top value=3.3k
R43 "RC0402JR-070RL" 0402 1908.84,1791.22 r90 top value=0
R44 "RC0402JR-070RL" 0402 2197.09,1804.12 r180 top value=0
R45 "CRCW0402100KFKED" 0402 2289.62,644.67 r90 top value=100k
R46 "CRCW0402100KFKED" 0402 2172,647.47 r90 top value=100k
R47 "RC0402JR-070RL" 0402 3434.95,1066.08 r270 top value=0
R48 "RC0402JR-070RL" 0402 3487.28,1065.24 r270 top value=0
R49 "RC0402JR-070RL" 0402 3540.79,1066.08 r270 top value=0
R50 "RC0402JR-070RL" 0402 3591,1066.08 r270 top value=0
R51 "RC0402JR-070RL" 0402 2628.61,1631.03 r270 top value=0
R52 "RC0402JR-070RL" 0402 2783.88,1276 r180 top value=0
R53 "RC0402JR-070RL" 0402 2679.61,1631.03 r270 top value=0
R54 "RC0402JR-070RL" 0402 2729.61,1631.03 r270 top value=0
R57 "ERJ-2RKF1002X" 0402 2989.47,434.99 r0 top value=10.0k
R59 "CRCW0603249KFKEA" 0603 3302.27,858.79 r0 top value=249k
R60 "RC0402FR-074K99L" 0402 2172,745.95 r90 top value=4.99k
R61 "CRCW04020000Z0ED" 0402 2967.81,759.62 r90 top value=0
R62 "RC0402JR-070RL" 0402 2759.67,2049.76 r0 top value=0
R65 "RC0402JR-070RL" 0402 2960.11,984.53 r180 top value=0
R66 "RC0402JR-070RL" 0402 2781.61,1631.03 r270 top value=0
R67 "RC0402JR-070RL" 0402 3047.75,957.05 r270 top value=0
R68 "CRCW04023R48FKED" 0402 1781.26,518.58 r90 top value=3.48
R69 "RC0402FR-074K99L" 0402 798.98,1413.34 r180 top value=4.99k
R70 "CRCW04021K65FKED" 0402 684.94,1413.01 r180 top value=1.65k
R71 "RC0402FR-074K99L" 0402 740.61,1470.52 r0 top value=4.99k
R72 "RK73Z1ETTP" 0402 2406.72,604.94 r270 top value=0
R73 "RK73Z1ETTP" 0402 2458.65,604.94 r270 top value=0
R74 "RK73Z1ETTP" 0402 2553.51,607.4 r90 top value=0
R75 "RK73Z1ETTP" 0402 2607.18,607.4 r90 top value=0
R76 "RK73Z1ETTP" 0402 2553.51,725.51 r90 top value=0
R77 "RK73Z1ETTP" 0402 2607.18,725.51 r90 top value=0
R78 "RC0402JR-070RL" 0402 2350.12,1052.43 r180 top value=0
R79 "CRCW040220K0FKED" 0402 740.61,1525.63 r0 top value=20.0k
R80 "RC0402JR-070RL" 0402 2832.61,1631.03 r270 top value=0
R81 "RC0402JR-070RL" 0402 3081.09,1893.14 r270 top value=0
R82 "RC0402JR-070RL" 0402 2783.88,1136.27 r180 top value=0
R83 "RC0402JR-070RL" 0402 2783.88,1228.82 r180 top value=0
R84 "RC0402JR-070RL" 0402 2783.88,1183.01 r180 top value=0
R85 "CRCW040210K0FKED" 0402 3406.78,1553.48 r180 top value=10.0k
S1 "B3U-1000P" SW_B3U-1000P 2599.13,998.31 r270 top
S2 "B3U-1000P" SW_B3U-1000P 2037.41,1815.93 r180 top
S3 "B3U-1000P" SW_B3U-1000P 3497.51,1764.3 r0 top
TP1 "VSYS" Keystone5010 1398.47,562.18 r0 top
TP2 "VIN" Keystone5010 1398.47,120.25 r0 top
TP3 "GND" Keystone5011 1398.47,337.77 r0 top
TP4 "GND" Keystone5011 422.34,120.25 r0 top
TP5 "S1751-46" Harwin_S1751-46#1 1190.75,371.98 r180 bottom
TP6 "3V3" Keystone5010 415.57,1122.14 r90 top
TP7 "GND" Keystone5011 602.92,1122.14 r270 top
TP8 "VBUS" Keystone5010 1670.79,120.25 r90 top
TP9 "S1751-46" Harwin_S1751-46#2 1551.79,557.34 r180 bottom
TP10 "S1751-46" Harwin_S1751-46#3 435.45,1008.91 r0 bottom
TP11 "GND" Keystone5011 2161.32,120.25 r90 top
TP12 "S1751-46" Harwin_S1751-46#4 587.04,373.2 r180 bottom
TP15 "S1751-46" Harwin_S1751-46#5 3076.43,643.74 r180 bottom
TP17 "S1751-46" Harwin_S1751-46#6 2172.78,240.25 r270 bottom
TP18 "S1751-46" Harwin_S1751-46#1 1914.71,159.21 r180 bottom
TP19 "S1751-46" Harwin_S1751-46#1 850.16,1783.27 r180 bottom
TP20 "S1751-46" Harwin_S1751-46#1 705.45,1785.15 r180 bottom
TP21 "S1751-46" Harwin_S1751-46#1 559.29,1788 r180 bottom
TP22 "S1751-46" Harwin_S1751-46#7 409.68,1776.88 r180 bottom
U1 "LM76005RNPR" RNP0030A 1070.06,1428.65 r270 top
U2 "LMR36506R3RPET" RPE0009A 795.33,719.68 r180 top
U3 "TVS2200DRVR" DRV0006A 1857.8,729.86 r0 top
U4 "TPS65987DDHRSHR" RSH0056E 2090.45,1021.42 r90 top
U5 "W25Q80DVSNIG" SOIC-8 1994.33,1578.58 r270 top
U6 "TM4C123GH6PMTR" PM0064A_L 3137.37,1296.2 r90 top
U8 "TPD2E009DRTR" DRT0003A 3157.06,309.41 r90 top
U9 "TPS76833QD" D0008A_N 3164.66,710.41 r0 top
U10 "TPD6S300ARUKR" RUK0020B_NV 2438.22,353.4 r270 top
Y1 "NX3225GA-16.000M-STD-CRG-1" NDK_NX3225GA 3192.46,1681.52 r0 top

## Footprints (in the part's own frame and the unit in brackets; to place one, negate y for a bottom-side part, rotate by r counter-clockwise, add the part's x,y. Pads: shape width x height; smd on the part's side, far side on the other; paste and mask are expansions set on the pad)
0402 [mm] "0402 from SM-752 data"
  rect 0.8x0.6 smd: 1(-0.6,0) 2(0.6,0)
  silkscreen extent -1.22,-0.52 1.22,0.52, body extent -0.55,-0.3 0.55,0.3, height 0.6
0402_080 [mm] "SMD, 2-Leads, Body 1x0.5mm"
  rect 0.8x0.6 smd: 1(-0.6,0) 2(0.6,0)
  silkscreen extent -1.22,-0.52 1.22,0.52, body extent -0.65,-0.4 0.65,0.4, height 0.8
0402L [mm] "0402 from SM-752 data"
  rect 0.6x0.5 smd: 1(-0.5,0) 2(0.5,0)
  body extent -0.55,-0.3 0.55,0.3, height 0.6
0603 [mm] "0603 from SM-752 data"
  rect 1x0.95 smd: 1(-0.8,0) 2(0.8,0)
  silkscreen extent -1.52,-0.69 1.52,0.69, body extent -0.87,-0.47 0.87,0.47, height 1
0805_HV [mil] "0805 with 30mil clearance between pads"
  rect 50x63 smd: 1(-40,0) 2(40,0)
  silkscreen extent -74,-40 74,40, body extent -43,-29 43,29, height 57
1206 [mm] "1206 from SM-752 data"
  rect 1.3x1.85 smd: 1(-1.45,0) 2(1.45,0)
  silkscreen extent -2.4,-1.21 2.4,1.21, body extent -1.7,-0.9 1.7,0.9, height 1.35
1206_190 [mm] "1206_190"
  rect 1.1x1.6 smd: 1(-1.7,0) 2(1.7,0)
  silkscreen extent -0.9,-1 0.9,1, body extent -1.75,-0.95 1.75,0.95, height 1.9
1210_280 [mm] "SMD, 2-Leads, Body 3.6x2.8mm, Height 2.8mm"
  rect 1.1x2.2 smd: 1(-1.65,0) 2(1.65,0)
  silkscreen extent -0.84,-1.4 0.84,1.4, body extent -1.8,-1.4 1.8,1.4, height 2.8
3528-21 [mm] "Medium Density IPC, based on Kemet datasheet 2016-10-20"
  rrect6% 1.8x2.23 smd: 1(-1.46,0) 2(1.46,0)
  silkscreen extent -2.29,-1.5 0.76,1.5, body extent -1.85,-1.5 1.85,1.5, height 2.12
CE_Mark_5mm [mil] "Minimum text height for CE Mark"
  silkscreen extent -138,-98 138,98
CONN_PEC05DAAN [mm] "SULLINS"
  rect 1.65x1.65 hole 1.016 mask+0: 1(-5.08,-1.27)
  round 1.65 hole 1.016 mask+0: 2(-5.08,1.27) 3(-2.54,-1.27) 4(-2.54,1.27) 5(0,-1.27) 6(0,1.27) 7(2.54,-1.27) 8(2.54,1.27) 9(5.08,-1.27) 10(5.08,1.27)
  silkscreen extent -7.45,-2.6 6.35,2.54, body extent -6.35,-2.54 6.35,2.54, height 8.38
D0008A_N [mm] "SOIC, 8-Leads, Body 4.9x3.9mm, Pitch 1.27mm, IPC Medium Density"
  oval 1.45x0.6 smd: 1(-2.725,1.905) 2(-2.725,0.635) 3(-2.725,-0.635) 4(-2.725,-1.905) 5(2.725,-1.905) 6(2.725,-0.635) 7(2.725,0.635) 8(2.725,1.905)
  silkscreen extent -3.3,-2.5 0.9,2.5, body extent -3,-2.45 3,2.45, height 1.63
DPL0002A [mm] "R-PX2SON-N2"
  rect 0.18x0.25 smd: 1(-0.193,0)
  rect 0.19x0.25 smd: 2(0.193,0)
  body extent -0.32,-0.17 0.32,0.17, height 0.32
DRT0003A [mm] "SOTFL, 3-Leads, Body 1x1mm (inc leads), Pitch 0.35mm"
  rect 0.45x0.3 smd: 1(-0.575,0.35) 2(-0.575,-0.35) 3(0.575,0)
  silkscreen extent -0.03,-0.6 0.5,0.6, body extent -0.5,-0.5 0.5,0.5, height 0.5
DRV0006A [mm] "SON, 6-Leads, Body 2x2mm, Pitch 0.65mm, Thermal Pad 1.6x1mm, TI Recommended"
  rrect33% 0.45x0.3 smd: 1(-0.975,0.65) 2(-0.975,0) 3(-0.975,-0.65) 4(0.975,-0.65) 5(0.975,0) 6(0.975,0.65)
  rrect14% 1x0.7 on Top Paste: 7(0,-0.45) 7(0,0.45)
  rrect10% 1x1.6 smd paste-0.5: 7(0,0)
  silkscreen extent -1.05,-1.2 1.05,1.2, body extent -1.05,-1.05 1.05,1.05, height 0.81
DSN2_0603 [mm] "SMD, 2-Leads, Body 1.6x0.8mm"
  rect 0.52x0.7 smd: 1(-0.64,0)
  rect 1.05x0.7 smd: 2(0.275,0)
  silkscreen extent -1.4,-0.75 0.8,0.75, body extent -0.8,-0.4 0.8,0.4, height 0.31
FCC_disclaimer [mil]
FP-06031C101JAT2A_0603-MFG [mm]
  rrect13% 0.8x0.75 smd paste+0 mask+0: 1(-0.75,0) 2(0.75,0)
  silkscreen extent -0.87,-0.77 0.87,0.77, body extent -1.25,-0.58 1.25,0.58, height 0.25
FP-12402054M611A_CONN_USB-MFG [mm]
  rrect100% 0.9x1.9 hole 1.6 slot 0.6 at 0 deg paste-1000 mask+0: 1(-1.43,5.675) 2(1.43,5.675) 3(-1.43,0.825) 4(1.43,0.825)
  rrect17% 0.6x0.6 hole 0.4 paste-1000 mask+0: A1(-0.39,0.775)
  round 0.6 hole 0.4 paste-1000 mask+0: A4(-0.39,1.675) A5(-0.39,2.575) A6(-0.39,3.475) A7(-0.39,4.375) A9(-0.39,5.275) A12(-0.39,6.175) B1(0.39,5.725) B4(0.39,4.825) B5(0.39,3.925) B6(0.39,3.025) B7(0.39,2.125) B9(0.39,1.225) B12(0.39,0.325)
  silkscreen extent -2.61,-3.6 1.98,7.37, body extent -2.08,-7.47 2.08,7.47, height 0.25
FP-0436500301_CONN_HDR3-MFG [mm]
  rrect6% 1.57x1.57 hole 1.02 paste-1000 mask+0: 1(3,3.97)
  round 1.57 hole 1.02 paste-1000 mask+0: 2(0,3.97) 3(-3,3.97)
  round 3 hole 3 unplated paste-1000 mask+0: ""(0,-0.35)
  silkscreen extent -6.45,-5.07 6.45,5.67, body extent -6.55,-5.18 6.55,5.18, height 0.25
FP-CNC6P1X7R2A475K250AE_1210-MFG [mm]
  rrect9% 1.1x2.2 smd paste+0 mask+0: 1(-1.65,0) 2(1.65,0)
  silkscreen extent -0.72,-1.4 0.72,1.4, body extent -2.3,-1.5 2.3,1.5, height 0.25
FP-ZX62RD-AB-5P8(30)_CONN_USB-MFG [mm]
  rrect25% 0.4x1.35 smd paste+0 mask+0: 1(1.3,3.025) 2(0.65,3.025) 3(0,3.025) 4(-0.65,3.025) 5(-1.3,3.025)
  rrect100% 1.05x1.25 hole 0.85 slot 0.65 at 0 deg paste-1000 mask+0: 6(-2.225,3.35) 7(2.225,3.35)
  rrect100% 0.825x1.5 hole 1.5 slot 0.825 at 0 deg paste-1000: 8(-4.088,0.225)
  round 1.26 smd paste-1000 mask+0: 8(-4,0.225) 10(4,0.225)
  round 1.26 smd far side paste-1000 mask+0: 8(-4,0.225) 10(4,0.225)
  rrect5% 2.9x1.9 smd paste+0 mask+0: 9(0,0.225)
  rrect100% 0.825x1.5 hole 1.5 slot 0.825 at 0 deg paste-1000 mask+0: 10(4.088,0.225)
  Top Layer 1 region: 3.3,1.175 4.2,1.175 4.391,1.137 4.554,1.029 4.662,0.866 4.7,0.675 4.7,0.675 4.7,-0.225 4.662,-0.416 4.554,-0.579 4.391,-0.687 4.2,-0.725 4.2,-0.725 3.3,-0.725
  Top Layer 1 region: -3.3,-0.725 -4.2,-0.725 -4.391,-0.687 -4.554,-0.579 -4.662,-0.416 -4.7,-0.225 -4.7,-0.225 -4.7,0.675 -4.662,0.866 -4.554,1.029 -4.391,1.137 -4.2,1.175 -4.2,1.175 -3.3,1.175
  Bottom Layer 1 region: 3.3,1.175 4.2,1.175 4.391,1.137 4.554,1.029 4.662,0.866 4.7,0.675 4.7,0.675 4.7,-0.225 4.662,-0.416 4.554,-0.579 4.391,-0.687 4.2,-0.725 4.2,-0.725 3.3,-0.725
  Bottom Layer 1 region: -3.3,-0.725 -4.2,-0.725 -4.391,-0.687 -4.554,-0.579 -4.662,-0.416 -4.7,-0.225 -4.7,-0.225 -4.7,0.675 -4.662,0.866 -4.554,1.029 -4.391,1.137 -4.2,1.175 -4.2,1.175 -3.3,1.175
  silkscreen extent -4.95,1.55 4.95,4.33, body extent -4.33,-2.42 4.33,3.48, height 2.88
Harwin_S1751-46#1 [mil] "Test Point, Body 3.25x1.65mm"
  rect 35x35 smd: 1(0,0)
  body extent -64,-32 64,32, height 81
Harwin_S1751-46#2 [mil] "Test Point, Body 3.25x1.65mm"
  rect 35x35 smd: 1(2.74,4.84)
  body extent -64,-32 64,32, height 81
Harwin_S1751-46#3 [mil] "Test Point, Body 3.25x1.65mm"
  rect 35x35 smd: 1(-19.88,0)
  body extent -64,-32 64,32, height 81
Harwin_S1751-46#4 [mil] "Test Point, Body 3.25x1.65mm"
  rect 35x35 smd: 1(-231.26,113.67)
  body extent -64,-32 64,32, height 81
Harwin_S1751-46#5 [mil] "Test Point, Body 3.25x1.65mm"
  rect 35x35 smd: 1(69.24,-38.79)
  body extent -64,-32 64,32, height 81
Harwin_S1751-46#6 [mil] "Test Point, Body 3.25x1.65mm"
  rect 35x35 smd: 1(-25.5,-25.5)
  body extent -64,-32 64,32, height 81
Harwin_S1751-46#7 [mil] "Test Point, Body 3.25x1.65mm"
  rect 35x35 smd: 1(-6.16,13)
  body extent -64,-32 64,32, height 81
IEC_HighVoltage_Small [mil]
  silkscreen extent -107,-88 107,97
IEC_HotSurface_Small [mil]
  silkscreen extent -107,-93 107,92
Keystone5010 [mil] "Keystone Multipurpose loops"
  round 87 hole 63: 1(0,0)
  silkscreen extent -70,-70 70,70, body extent -63,-63 63,62, height 319
Keystone5011 [mil] "Keystone Multipurpose loops"
  round 87 hole 63: 1(0,0)
  silkscreen extent -70,-70 70,70, body extent -63,-63 63,62, height 319
Label_650x200 [mil] "Thermal Transfer Label"
  round 1 on Mech14: 0(0,0)
  silkscreen extent -325,-100 325,100, body extent -325,-100 325,100, height 1
"LW QH8G_White" [mm] "SMD, 2-Leads, Body 1x0.5mm"
  rect 0.6x0.6 smd paste-0.3: 1(-0.55,0) 2(0.55,0)
  silkscreen extent 1.1,-0.4 1.3,0.4, body extent -0.55,-0.3 0.55,0.3, height 0.4
NDK_NX3225GA [mm] "NDK"
  rect 1.2x1.4 smd: 1(-0.8,1.1) 2(-0.8,-1.1) 3(0.8,-1.1) 4(0.8,1.1)
  silkscreen extent -1.9,-0.1 1.4,2, body extent -1.3,-1.65 1.3,1.65, height 0.9
"NY PMS 440 0025 PH"#1 [mil] "4-40 nylon screw and mounting hole"
  round 300 hole 170: 1(0,0)
  body extent -130,-130 130,130, height 106
"NY PMS 440 0025 PH"#2 [mil] "4-40 nylon screw and mounting hole"
  round 300 hole 170: 1(-13.66,-27.43)
  body extent -130,-130 130,130, height 106
"NY PMS 440 0025 PH"#3 [mil] "4-40 nylon screw and mounting hole"
  round 300 hole 170: 1(6,-72.35)
  body extent -130,-130 130,130, height 106
PM0064A_L [mm] "Thin QFP, 64-Leads, Body 10x10mm, Pitch 0.5mm, IPC High Density"
  oval 1.25x0.25 smd: 1(-5.625,3.75) 2(-5.625,3.25) 3(-5.625,2.75) 4(-5.625,2.25) 5(-5.625,1.75) 6(-5.625,1.25) 7(-5.625,0.75) 8(-5.625,0.25) 9(-5.625,-0.25) 10(-5.625,-0.75) 11(-5.625,-1.25) 12(-5.625,-1.75) 13(-5.625,-2.25) 14(-5.625,-2.75) 15(-5.625,-3.25) 16(-5.625,-3.75) 33(5.625,-3.75) 34(5.625,-3.25) 35(5.625,-2.75) 36(5.625,-2.25) 37(5.625,-1.75) 38(5.625,-1.25) 39(5.625,-0.75) 40(5.625,-0.25) 41(5.625,0.25) 42(5.625,0.75) 43(5.625,1.25) 44(5.625,1.75) 45(5.625,2.25) 46(5.625,2.75) 47(5.625,3.25) 48(5.625,3.75)
  oval 0.25x1.25 smd: 17(-3.75,-5.625) 18(-3.25,-5.625) 19(-2.75,-5.625) 20(-2.25,-5.625) 21(-1.75,-5.625) 22(-1.25,-5.625) 23(-0.75,-5.625) 24(-0.25,-5.625) 25(0.25,-5.625) 26(0.75,-5.625) 27(1.25,-5.625) 28(1.75,-5.625) 29(2.25,-5.625) 30(2.75,-5.625) 31(3.25,-5.625) 32(3.75,-5.625) 49(3.75,5.625) 50(3.25,5.625) 51(2.75,5.625) 52(2.25,5.625) 53(1.75,5.625) 54(1.25,5.625) 55(0.75,5.625) 56(0.25,5.625) 57(-0.25,5.625) 58(-0.75,5.625) 59(-1.25,5.625) 60(-1.75,5.625) 61(-2.25,5.625) 62(-2.75,5.625) 63(-3.25,5.625) 64(-3.75,5.625)
  silkscreen extent -5.65,-4.35 4.35,4.55, body extent -6.01,-6.01 6.01,6.01, height 1.5
RNP0030A [mm] "QFN, 30-Leads, Body 6x4mm, Pitch 0.5mm, Thermal Pad 4.6x2.2mm"
  rrect40% 0.75x0.25 smd: 1(-1.825,2.5) 2(-1.825,2) 3(-1.825,1.5) 4(-1.825,1) 5(-1.825,0.5) 6(-1.825,0) 7(-1.825,-0.5) 8(-1.825,-1) 9(-1.825,-1.5) 10(-1.825,-2) 11(-1.825,-2.5) 16(1.825,-2.5) 17(1.825,-2) 18(1.825,-1.5) 19(1.825,-1) 20(1.825,-0.5) 21(1.825,0) 22(1.825,0.5) 23(1.825,1) 24(1.825,1.5) 25(1.825,2) 26(1.825,2.5)
  rrect40% 0.25x0.6 smd: 12(-0.75,-2.9) 13(-0.25,-2.9) 14(0.25,-2.9) 15(0.75,-2.9) 27(0.75,2.9) 28(0.25,2.9) 29(-0.25,2.9) 30(-0.75,2.9)
  rrect5% 2.2x4.6 smd paste-3: 31(0,0)
  rrect10% 0.98x0.96 on Top Paste: 31A(-0.59,1.74) 31A(-0.59,0.58) 31A(-0.59,-0.58) 31A(-0.59,-1.74) 31A(0.59,1.74) 31A(0.59,0.58) 31A(0.59,-0.58) 31A(0.59,-1.74)
  silkscreen extent -2.17,-3.18 2.17,3.18, body extent -2,-3 2,3, height 0.77
RPE0009A [mm] "VQFN, 9-Leads, Body 2x2.mm"
  rrect50% 0.2x0.2 smd paste+0: 1(-0.9,0.738) 4(-0.9,-0.738) 5(0.9,-0.738) 8(0.9,0.738)
  rrect40% 0.6x0.25 smd: 2(-0.9,0.25) 3(-0.9,-0.25) 6(0.9,-0.25) 7(0.9,0.25)
  rrect29% 0.35x1.3 smd paste-0.35: 9(0,0.55)
  Top Layer 1 region: -1.2,0.676 -1.2,0.801 -1.196,0.82 -1.185,0.836 -1.169,0.847 -1.15,0.851 -1.15,0.851 -0.9,0.851 -0.881,0.854 -0.865,0.865 -0.854,0.881 -0.85,0.901 -0.85,0.901 -0.85,1.151 -0.846,1.17 -0.835,1.186 -0.819,1.197 -0.8,1.201 -0.8,1.201 -0.5,1.201 -0.481,1.197 -0.465,1.186 -0.454,1.17 -0.45,1.151 -0.45,1.151 -0.45,0.676 -0.454,0.656 -0.465,0.64 -0.481,0.629 -0.5,0.626 -0.5,0.626 -1.15,0.626 -1.169,0.629 -1.185,0.64 -1.196,0.656 -1.2,0.676
  Top Layer 1 region: 1.2,0.676 1.2,0.801 1.196,0.82 1.185,0.836 1.169,0.847 1.15,0.851 1.15,0.851 0.9,0.851 0.881,0.854 0.865,0.865 0.854,0.881 0.85,0.901 0.85,0.901 0.85,1.151 0.846,1.17 0.835,1.186 0.819,1.197 0.8,1.201 0.8,1.201 0.5,1.201 0.481,1.197 0.465,1.186 0.454,1.17 0.45,1.151 0.45,1.151 0.45,0.676 0.454,0.656 0.465,0.64 0.481,0.629 0.5,0.626 0.5,0.626 1.15,0.626 1.169,0.629 1.185,0.64 1.196,0.656 1.2,0.676
  Top Layer 1 region: -1.2,-0.676 -1.2,-0.801 -1.196,-0.82 -1.185,-0.836 -1.169,-0.847 -1.15,-0.851 -1.15,-0.851 -0.9,-0.851 -0.881,-0.854 -0.865,-0.865 -0.854,-0.881 -0.85,-0.901 -0.85,-0.901 -0.85,-1.151 -0.846,-1.17 -0.835,-1.186 -0.819,-1.197 -0.8,-1.201 -0.8,-1.201 -0.5,-1.201 -0.481,-1.197 -0.465,-1.186 -0.454,-1.17 -0.45,-1.151 -0.45,-1.151 -0.45,-0.676 -0.454,-0.656 -0.465,-0.64 -0.481,-0.629 -0.5,-0.626 -0.5,-0.626 -1.15,-0.626 -1.169,-0.629 -1.185,-0.64 -1.196,-0.656 -1.2,-0.676
  Top Layer 1 region: 1.2,-0.676 1.2,-0.801 1.196,-0.82 1.185,-0.836 1.169,-0.847 1.15,-0.851 1.15,-0.851 0.9,-0.851 0.881,-0.854 0.865,-0.865 0.854,-0.881 0.85,-0.901 0.85,-0.901 0.85,-1.151 0.846,-1.17 0.835,-1.186 0.819,-1.197 0.8,-1.201 0.8,-1.201 0.5,-1.201 0.481,-1.197 0.465,-1.186 0.454,-1.17 0.45,-1.151 0.45,-1.151 0.45,-0.676 0.454,-0.656 0.465,-0.64 0.481,-0.629 0.5,-0.626 0.5,-0.626 1.15,-0.626 1.169,-0.629 1.185,-0.64 1.196,-0.656 1.2,-0.676
  body extent -1,-1 1,1, height 1
RSH0056E [mm] "SMD, 56-Leads, Body 7x7mm, Pitch 0.4mm"
  rrect67% 0.8x0.3 smd paste-0.05 mask-0.05: 1(-3.35,2.6) 2(-3.35,2.2) 3(-3.35,1.8) 4(-3.35,1.4) 5(-3.35,1) 6(-3.35,0.6) 7(-3.35,0.2) 8(-3.35,-0.2) 9(-3.35,-0.6) 10(-3.35,-1) 11(-3.35,-1.4) 12(-3.35,-1.8) 13(-3.35,-2.2) 14(-3.35,-2.6) 29(3.35,-2.6) 30(3.35,-2.2) 31(3.35,-1.8) 32(3.35,-1.4) 33(3.35,-1) 34(3.35,-0.6) 35(3.35,-0.2) 36(3.35,0.2) 37(3.35,0.6) 38(3.35,1) 39(3.35,1.4) 40(3.35,1.8) 41(3.35,2.2) 42(3.35,2.6)
  rrect67% 0.3x0.8 smd paste-0.05 mask-0.05: 15(-2.6,-3.35) 16(-2.2,-3.35) 17(-1.8,-3.35) 18(-1.4,-3.35) 19(-1,-3.35) 20(-0.6,-3.35) 21(-0.2,-3.35) 22(0.2,-3.35) 23(0.6,-3.35) 24(1,-3.35) 25(1.4,-3.35) 26(1.8,-3.35) 27(2.2,-3.35) 28(2.6,-3.35) 43(2.6,3.35) 44(2.2,3.35) 45(1.8,3.35) 46(1.4,3.35) 47(1,3.35) 48(0.6,3.35) 49(0.2,3.35) 50(-0.2,3.35) 51(-0.6,3.35) 52(-1,3.35) 53(-1.4,3.35) 54(-1.8,3.35) 55(-2.2,3.35) 56(-2.6,3.35)
  rrect16% 1.47x1.15 on Top Paste: 57(-1.875,0.775) 57(-1.875,2.125) 58(-1.875,-2.15) 58(-1.875,-0.8)
  rrect6% 1.75x2.6 smd paste-2.2: 57(-1.875,1.45)
  rrect6% 1.75x2.55 smd paste-2.2: 58(-1.875,-1.475)
  rrect12% 1.47x1.12 on Top Paste: 59(0.215,1.98) 59(0.215,0.66) 59(0.215,-0.66) 59(0.215,-1.98) 59(1.885,-1.98) 59(1.885,-0.66) 59(1.885,0.66) 59(1.885,1.98)
  rrect3% 3.4x5.5 smd paste-2.2: 59(1.05,0)
  Top Layer 1 region: -3.75,-2.6 -2.95,-2.6 -2.95,-2.2 -3.75,-2.2
  Top Layer 1 region: -3.75,-1.8 -2.95,-1.8 -2.95,-1.4 -3.75,-1.4
  Top Layer 1 region: -3.75,1.4 -2.95,1.4 -2.95,1.8 -3.75,1.8
  Top Layer 1 region: -3.75,2.2 -2.95,2.2 -2.95,2.6 -3.75,2.6
  silkscreen extent -3.7,-3.7 3.7,3.7, body extent -3.57,-3.57 3.57,3.57, height 1.01
RUK0020B_NV [mm]
  rrect50% 0.6x0.2 smd: 1(-1.4,0.8) 2(-1.4,0.4) 3(-1.4,0) 4(-1.4,-0.4) 5(-1.4,-0.8) 11(1.4,-0.8) 12(1.4,-0.4) 13(1.4,0) 14(1.4,0.4) 15(1.4,0.8)
  rrect50% 0.2x0.6 smd: 6(-0.8,-1.4) 7(-0.4,-1.4) 8(0,-1.4) 9(0.4,-1.4) 10(0.8,-1.4) 16(0.8,1.4) 17(0.4,1.4) 18(0,1.4) 19(-0.4,1.4) 20(-0.8,1.4)
  rrect13% 0.75x0.75 on Top Paste: 21(-0.475,0.475) 21(-0.475,-0.475) 21(0.475,0.475) 21(0.475,-0.475)
  rrect6% 1.7x1.7 smd paste-0.85: 21(0,0)
  silkscreen extent -1.68,-1.68 1.68,1.68, body extent -1.5,-1.5 1.5,1.5, height 0.8
Samtec_HTSW-102-09-x-S [mm] "Header, 2x1, 2.54mm, TH"
  rect 1.55x1.55 hole 1.02: 1(-1.27,0)
  round 1.55 hole 1.02: 2(1.27,0)
  silkscreen extent -2.54,-1.24 2.54,1.6, body extent -2.54,-1.24 2.54,1.24, height 8.38
SOIC-8 [mm] "duplicate of SO-8.  SOIC, 8-Leads, Body 5.0x4.0mm (max), Pitch 1.27mm, IPC Medium Density"
  rrect17% 1.45x0.6 smd: 1(-2.725,1.905) 2(-2.725,0.635) 3(-2.725,-0.635) 4(-2.725,-1.905) 5(2.725,-1.905) 6(2.725,-0.635) 7(2.725,0.635) 8(2.725,1.905)
  silkscreen extent -3.5,-2.5 0.9,2.5, body extent -3,-2.45 3,2.45, height 1.63
SOT-23 [mm] "SOT23, 3-Leads, Body 2.9x1.3mm, Pitch 0.95mm, Lead Span 2.5mm, IPC Medium Density"
  rrect50% 1x0.6 smd: 1(-1.2,0.95) 2(-1.2,-0.95) 3(1.2,0)
  silkscreen extent -1.63,-1.5 0.7,1.5, body extent -1.16,-1.45 1.21,1.45, height 1
SW_B3U-1000P [mm] "OMRON"
  rect 0.8x1.7 smd: 1(-1.7,0) 2(1.7,0)
  silkscreen extent -1.5,-1.25 1.5,1.25, body extent -1.5,-1.25 1.5,1.25, height 1.75
TI_Stacked_Overlay_Small [mil]
  silkscreen extent -418,-98 418,98
WE-PD_1210 [mm] "Wurth Elektronik recommended land pattern"
  rect 2.9x5.4 smd: 1(-4.95,0) 2(4.95,0)
  silkscreen extent -6,-6 6,6, body extent -6,-6 6,6, height 10.01
WE-TPC-LH [mm] "Wurth Elektronik recommended land pattern, 2009-01-15"
  rect 0.5x0.5 smd: 1(-2.7,0) 2(2.7,0)
  Top Layer 1 region: -0.95,3.15 -0.95,3.15 -0.95,1.987 -1.228,1.838 -1.563,1.563 -1.838,1.228 -2.042,0.846 -2.168,0.431 -2.211,0 -2.168,-0.431 -2.042,-0.846 -1.838,-1.228 -1.563,-1.563 -1.228,-1.838 -0.95,-1.987 -0.95,-3.15 -3.15,-3.15 -3.15,-3.15 -3.15,3.15 -0.95,3.15
  Top Layer 1 region: 0.95,3.15 0.95,3.15 0.95,1.987 1.228,1.838 1.563,1.563 1.838,1.228 2.042,0.846 2.168,0.431 2.211,0 2.168,-0.431 2.042,-0.846 1.838,-1.228 1.563,-1.563 1.228,-1.838 0.95,-1.987 0.95,-3.15 3.15,-3.15 3.15,-3.15 3.15,3.15 0.95,3.15
  silkscreen extent -3.4,-3.4 3.4,3.4, body extent -3.05,-3.05 3.05,3.05, height 3
WEEE_Minimum [mil] "WEEElie bin"
  silkscreen extent -95,-172 99,104

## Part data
C1: library part CMP-0007370-4, "CAP, CERM, 2.2 uF, 10 V, +/- 10%, X7R, 0603", Cap_Case=0603, Manufacturer=MuRata, Supplier Part Number 1=490-4520-1-ND, TempCo=X7R, Tolerance_%=10%, Value1="0.009 ohm", Value2=10V, ValueDisplayed=2.2uF
C2 C3 C4 C5: library part CMP-0082266-1, "CAP, CERM, 22 µF, 25 V,+/- 10%, X7R, 1210", Cap_Case=1210, Manufacturer=Kemet, Supplier Part Number 1=399-11958-1-ND, TempCo=X7R, Tolerance_%=10%, Value1="0.001 ohm", Value2=25V, ValueDisplayed=22µF
C6: library part CMP-0007011-5, "CAP, CERM, 1 uF, 50 V, +/- 10%, X5R, 0603", Cap_Case=0603, Manufacturer=TDK, Supplier Part Number 1=445-7468-1-ND, TempCo=X5R, Tolerance_%=10%, Value1="0.005522 ohm", Value2=50V, ValueDisplayed=1uF
C7: library part CMP-0006196-2, "CAP, CERM, 100 pF, 50 V, +/- 1%, C0G/NP0, 0402", Cap_Case=0402, Manufacturer=AVX, Supplier Part Number 1=478-3658-1-ND, TempCo=C0G/NP0, Tolerance_%=1%, Value1=Unknown, Value2=50V, ValueDisplayed=100pF
C8 C9 C10 C11: library part CMP-0094503-1, "4.7 µF ±10% 100V Ceramic Capacitor X7R 1210 (3225 Metric)", Digikey Part Number=445-181657-1-ND, Manufacturer=TDK, Mouser Part Number=810-CNC6P1X7R2A475K2, Operating Temperature Range="-55°C to +125°C", TempCo=15%, Temperature Characteristic=X7R, Tolerance_%=10%, ValueDisplayed=4.7uF
C12: library part CMP-0007060-4, "CAP, CERM, 0.047 uF, 100 V, +/- 10%, X7S, 0603", Cap_Case=0603, Manufacturer=TDK, Supplier Part Number 1=445-6032-1-ND, TempCo=X7S, Tolerance_%=10%, Value1="0.089796 ohm", Value2=100V, ValueDisplayed=0.047uF
C13: library part CMP-0006669-2, "CAP, CERM, 0.047 uF, 25 V, +/- 10%, X7R, 0402", Cap_Case=0402, Manufacturer=MuRata, Supplier Part Number 1=490-3254-1-ND, TempCo=X7R, Tolerance_%=10%, Value1=Unknown, Value2=25V, ValueDisplayed=0.047uF
C14: library part CMP-0007052-4, "CAP, CERM, 1 uF, 35 V, +/- 10%, X7R, 0603", Cap_Case=0603, Manufacturer=TDK, Supplier Part Number 1=445-7414-1-ND, TempCo=X7R, Tolerance_%=10%, Value1=Unknown, Value2=35V, ValueDisplayed=1uF
C15: library part CMP-0007377-4, "CAP, CERM, 0.01 uF, 16 V, +/- 10%, X7R, 0603", Cap_Case=0603, Manufacturer=MuRata, Supplier Part Number 1=490-1525-1-ND, TempCo=X7R, Tolerance_%=10%, Value1=Unknown, Value2=16V, ValueDisplayed=0.01uF
C16: library part CMP-0860555-1, "CAP, CERM, 0.1 µF, 25 V,+/- 10%, X7R, 0402", Cap_Case=0402, Manufacturer=Yageo, TempCo=X7R, Tolerance_%=10%, Value2=25V, ValueDisplayed=0.1µF
C17: library part CMP-0008971-3, "CAP, CERM, 2.2 uF, 100 V, +/- 10%, X7R, 1206_190", Cap_Case=1206, Manufacturer=MuRata, Supplier Part Number 1=490-7209-1-ND, TempCo=X7R, Tolerance_%=10%, Value1=Unknown, Value2=100V, ValueDisplayed=2.2uF
C18: library part CMP-0085537-1, "CAP, CERM, 1 µF, 16 V,+/- 10%, X7R, 0603", Cap_Case=0603, Manufacturer="Samsung Electro-Mechanics", TempCo=X7R, Tolerance_%=10%, Value2=16V, ValueDisplayed=1µF
C19 C20: library part CMP-0008377-2, "CAP, CERM, 22 uF, 10 V, +/- 20%, X7R, 0805", Cap_Case=0805, Manufacturer=MuRata, Supplier Part Number 1=81-GRM21BZ71A226ME5L, TempCo=X7R, Tolerance_%=20%, Value1=Unknown, Value2=10V, ValueDisplayed=22uF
